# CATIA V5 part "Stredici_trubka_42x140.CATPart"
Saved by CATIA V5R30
Part number: Stredici_trubka_42x140
Definition: E 1160_42x140_3
Nomenclature: E 1160_42x140_3
Source: Unknown
Description: PART--DESC
Bounding box of the stored display mesh (mm): x -208 to -166, y -157.99 to -116.01, z -258 to -118
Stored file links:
  E:\Bakalarka\Model\Forma_v7\Stredici_trubka_42x140.CATPart
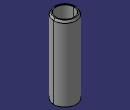
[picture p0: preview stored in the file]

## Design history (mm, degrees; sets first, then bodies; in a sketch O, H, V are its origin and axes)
Body1 "MANIFOLD_SOLID_BREP #3882" (main body)
  Solid1: solid without history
